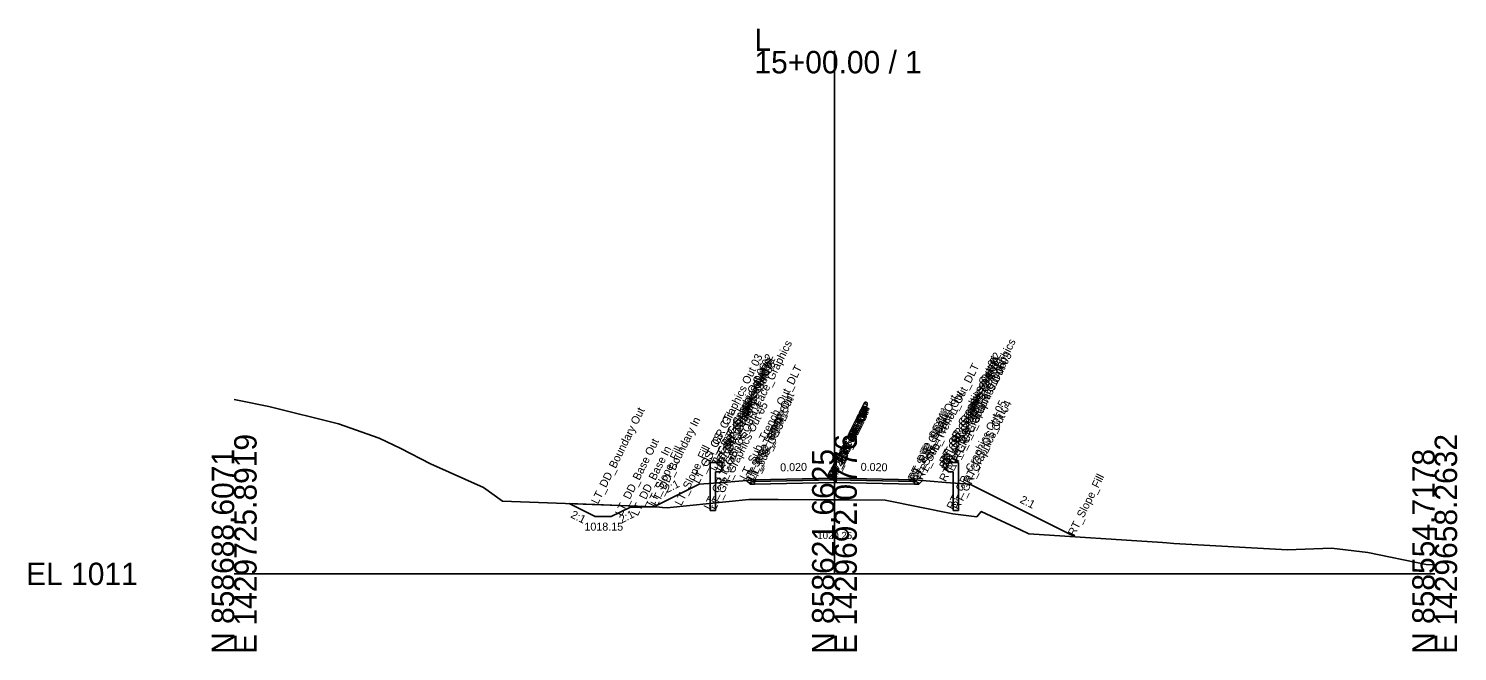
# Model space of a CAD drawing. Extents: x -26 to 153, y -10 to 13058.
# Drawn here: x -25.7 to 152.8, y 6990.3 to 7068.1 of the extents above; entities that cross this region are included whole.
import ezdxf

# ---------------------------------------------------------------- set-up
doc = ezdxf.new("R2010")
doc.units = 0
for name, color, linetype in [('Default', 7, 'Continuous'), ('Exist Cross Section Cell', 7, 'Continuous'), ('Exist XS Ground Line', 7, 'Continuous'), ('Old_Level_50', 7, 'Continuous'), ('Prop CMT Ditch DDE', 7, 'Continuous'), ('Prop CMT Guardrail Graphics', 7, 'Continuous'), ('Prop CMT Pvmt Course 1', 7, 'Continuous'), ('Prop CMT Pvmt Course 2', 7, 'Continuous'), ('Prop CMT Pvmt Surface', 7, 'Continuous'), ('Prop CMT Pvmt Surface Shoulder', 7, 'Continuous'), ('Prop CMT Shld Paved Course 1', 7, 'Continuous'), ('Prop CMT Shld Paved Course 2', 7, 'Continuous'), ('Prop CMT Slope Grass', 7, 'Continuous'), ('Prop CMT Subgrade Daylight Point', 7, 'Continuous'), ('Prop CMT Subgrade Earthwork', 7, 'Continuous'), ('Prop XS Ditch Slope Text', 7, 'Continuous'), ('Prop XS Ditch Standard Text', 7, 'Continuous'), ('Prop XS Dump Level', 7, 'Continuous'), ('Prop XS SE Text', 7, 'Continuous'), ('Prop XS Side Slope Text', 7, 'Continuous')]:
    doc.layers.add(name, color=color, linetype=linetype)

msp = doc.modelspace()

# ---------------------------------------------------------------- linework, layer by layer
at = {"layer": 'Exist Cross Section Cell'}
for p, q in [((75, 7000), (75, 7065.35)), ((0, 7000), (75, 7000)), ((75, 7000), (150, 7000))]:
    msp.add_line(p, q, dxfattribs=at)
at = {"layer": 'Exist XS Ground Line'}
msp.add_lwpolyline([(0, 7021.78), (0.6, 7021.68), (4.31, 7020.91), (13.04, 7018.73), (18.11, 7016.97), (20.83, 7015.68), (24.54, 7013.75), (31.15, 7010.81), (33.52, 7009.1), (51.47, 7008.4), (53.16, 7008.34), (53.53, 7008.29), (54.16, 7008.26), (54.47, 7008.3), (64.29, 7009.29), (67.98, 7009.31), (72.67, 7009.26), (75, 7009.25), (76.9, 7009.24), (81.34, 7009.19), (89.78, 7007.51), (92.77, 7007.11), (93.34, 7007.8), (98.26, 7005.49), (99.29, 7005.02), (115.98, 7003.94), (116.55, 7003.86), (117.4, 7003.81), (131.59, 7002.99), (137.11, 7003.23), (141.63, 7002.65), (148.95, 7001.18), (150, 7001.13)], dxfattribs=at)
at = {"layer": 'Old_Level_50'}
for p, q in [((51.47, 7008.4), (41.87, 7008.78)), ((49.42, 7008.3), (52.42, 7008.36)), ((52.42, 7008.36), (51.47, 7008.4))]:
    msp.add_line(p, q, dxfattribs=at)
msp.add_lwpolyline([(41.87, 7008.78), (45.12, 7007.15), (47.12, 7007.15), (49.42, 7008.3)], dxfattribs=at)
at = {"layer": 'Prop CMT Ditch DDE'}
for points in [[(49.42, 7008.3), (47.12, 7007.15), (45.12, 7007.15), (41.87, 7008.78)], [(49.42, 7008.3), (52.42, 7008.36)]]:
    msp.add_lwpolyline(points, dxfattribs=at)
at = {"layer": 'Prop CMT Guardrail Graphics'}
for points in [[(59.48, 7007.93), (59.48, 7013.93)], [(59.48, 7013.93), (60.81, 7013.93), (61.08, 7013.64)], [(61.08, 7013.06), (60.81, 7012.77), (60.15, 7012.77)], [(60.15, 7012.77), (60.15, 7007.93)], [(61.08, 7013.64), (60.81, 7013.35)], [(60.81, 7013.35), (61.08, 7013.06)], [(90.52, 7013.93), (89.19, 7013.93), (88.92, 7013.64)], [(88.92, 7013.64), (89.19, 7013.35)], [(89.19, 7013.35), (88.92, 7013.06)], [(88.92, 7013.06), (89.19, 7012.77), (89.85, 7012.77)], [(89.85, 7012.77), (89.85, 7007.93)], [(90.52, 7007.93), (90.52, 7013.93)], [(60.15, 7007.93), (59.48, 7007.93)], [(89.85, 7007.93), (90.52, 7007.93)]]:
    msp.add_lwpolyline(points, dxfattribs=at)
at = {"layer": 'Prop CMT Pvmt Course 1'}
for points in [[(75, 7011.95), (65, 7011.75)], [(65, 7011.75), (65, 7011.54)], [(65, 7011.54), (75, 7011.74)], [(75, 7011.74), (75, 7011.95)], [(75, 7011.95), (85, 7011.75)], [(75, 7011.74), (75, 7011.95)], [(85, 7011.54), (75, 7011.74)], [(85, 7011.75), (85, 7011.54)]]:
    msp.add_lwpolyline(points, dxfattribs=at)
msp.add_lwpolyline([(75, 7011.74), (75, 7011.82), (75, 7011.82), (75, 7011.74)], close=True, dxfattribs=at)
msp.add_lwpolyline([(75, 7011.74), (75, 7011.82), (75, 7011.82), (75, 7011.74)], close=True, dxfattribs=at)
at = {"layer": 'Prop CMT Pvmt Course 2'}
for points in [[(75, 7011.74), (65, 7011.54)], [(65, 7011.54), (65, 7011.21)], [(65, 7011.21), (75, 7011.41)], [(75, 7011.41), (75, 7011.74)], [(75, 7011.41), (75, 7011.74)], [(75, 7011.74), (85, 7011.54)], [(85, 7011.21), (75, 7011.41)], [(85, 7011.54), (85, 7011.21)]]:
    msp.add_lwpolyline(points, dxfattribs=at)
at = {"layer": 'Prop CMT Pvmt Surface'}
for points in [[(75, 7011.95), (65, 7011.75)], [(75, 7011.95), (85, 7011.75)]]:
    msp.add_lwpolyline(points, dxfattribs=at)
at = {"layer": 'Prop CMT Pvmt Surface Shoulder'}
for points in [[(65, 7011.75), (65, 7011.75)], [(85, 7011.75), (85, 7011.75)]]:
    msp.add_lwpolyline(points, dxfattribs=at)
at = {"layer": 'Prop CMT Shld Paved Course 1'}
for points in [[(65, 7011.75), (64.79, 7011.53)], [(64.79, 7011.53), (65, 7011.54)], [(65, 7011.75), (65, 7011.75)], [(65, 7011.54), (65, 7011.75)], [(85, 7011.75), (85, 7011.75)], [(85, 7011.75), (85.21, 7011.53)], [(85, 7011.54), (85, 7011.75)], [(85.21, 7011.53), (85, 7011.54)]]:
    msp.add_lwpolyline(points, dxfattribs=at)
at = {"layer": 'Prop CMT Shld Paved Course 2'}
for points in [[(64.79, 7011.53), (64.45, 7011.19)], [(64.45, 7011.19), (65, 7011.21)], [(65, 7011.54), (64.79, 7011.53)], [(64.79, 7011.53), (64.79, 7011.53)], [(65, 7011.21), (65, 7011.54)], [(85, 7011.54), (85.21, 7011.53)], [(85, 7011.21), (85, 7011.54)], [(85.55, 7011.19), (85, 7011.21)], [(85.21, 7011.53), (85.21, 7011.53)], [(85.21, 7011.53), (85.55, 7011.19)]]:
    msp.add_lwpolyline(points, dxfattribs=at)
at = {"layer": 'Prop CMT Slope Grass'}
for points in [[(58.08, 7011.19), (52.42, 7008.36)], [(61.08, 7011.43), (58.08, 7011.19)], [(65, 7011.75), (61.08, 7011.43)], [(85, 7011.75), (88.92, 7011.43)], [(88.92, 7011.43), (91.92, 7011.19)], [(91.92, 7011.19), (105, 7004.65)]]:
    msp.add_lwpolyline(points, dxfattribs=at)
at = {"layer": 'Prop CMT Subgrade Earthwork'}
for points in [[(64.45, 7011.19), (63.98, 7011.67)], [(65, 7011.21), (64.45, 7011.19)], [(75, 7011.41), (65, 7011.21)], [(75, 7011.41), (85, 7011.21)], [(85, 7011.21), (85.55, 7011.19)], [(85.55, 7011.19), (86.02, 7011.67)]]:
    msp.add_lwpolyline(points, dxfattribs=at)

# ---------------------------------------------------------------- texts
at = {"layer": 'Default'}
msp.add_text('-', height=0.0001, dxfattribs=at).set_placement((0, 7000))
at = {"layer": 'Exist Cross Section Cell'}
for s, p in [('L', (65, 7065.35)), ('15+00.00 / 1', (65, 7062.55)), ('EL 1011', (-26, 6998.6))]:
    msp.add_text(s, height=2.8, dxfattribs=at).set_placement(p)
for s, p in [('E 1429725.8919', (2.8, 6990)), ('E 1429692.0776', (77.8, 6990)), ('E 1429658.2632', (152.8, 6990)), ('N 858688.6071', (0, 6990)), ('N 858621.6625', (75, 6990)), ('N 858554.7178', (150, 6990))]:
    msp.add_text(s, height=2.8, rotation=90, dxfattribs=at).set_placement(p)
at = {"layer": 'Prop CMT Subgrade Daylight Point'}
msp.add_text('1020.25', height=0.9, dxfattribs=at).set_placement((72.86, 7004.35))
at = {"layer": 'Prop XS Ditch Slope Text'}
for rotation, p in [(333.4349, (41.96, 7007.09)), (26.5651, (48.42, 7006.3))]:
    msp.add_text('2:1', height=1, rotation=rotation, dxfattribs=at).set_placement(p)
at = {"layer": 'Prop XS Ditch Standard Text'}
msp.add_text('1018.15', height=1, dxfattribs=at).set_placement((43.76, 7005.4))
at = {"layer": 'Prop XS Dump Level'}
for s, p in [('LT_GS_OS_GR_Face_Graphics', (61.08, 7011.43)), ('RT_GS_OS_GR_Face_Graphics', (88.92, 7011.43)), ('LT_GR_Graphics Out 03', (59.48, 7013.93)), ('LT_GR_Graphics Out 02', (60.81, 7013.93)), ('LT_GR_Graphics Out 01', (61.08, 7013.64)), ('RT_GR_Graphics Out 01', (88.92, 7013.64)), ('RT_GR_Graphics Out 02', (89.19, 7013.93)), ('RT_GR_Graphics Out 09', (89.19, 7013.35)), ('RT_GR_Graphics Out 03', (90.52, 7013.93)), ('LT_GR_Graphics Out 06', (60.15, 7012.77)), ('LT_GR_Graphics Out 09', (60.81, 7013.35)), ('LT_GR_Graphics Out 07', (60.81, 7012.77)), ('LT_GR_Graphics Out 08', (61.08, 7013.06)), ('LT_Sub_Trench_Out_DLT', (63.98, 7011.67)), ('RT_Sub_Trench_Out_DLT', (86.02, 7011.67)), ('RT_GR_Graphics Out 08', (88.92, 7013.06)), ('RT_GR_Graphics Out 07', (89.19, 7012.77)), ('RT_GR_Graphics Out 06', (89.85, 7012.77)), ('LT_Sub_Trench_Out', (64.45, 7011.19)), ('LT_PS2_Shelf_Out', (64.79, 7011.53)), ('RT_PS2_Shelf_Out', (85.21, 7011.53)), ('RT_Sub_Trench_Out', (85.55, 7011.19)), ('RT_GR_Graphics Out 05', (89.85, 7007.93)), ('LT_DD_Boundary Out', (45.44, 7008.63)), ('LT_GS_OS_CTL', (58.08, 7011.19)), ('LT_GR_Graphics Out 04', (59.48, 7007.93)), ('LT_GR_Graphics Out 05', (60.15, 7007.93)), ('LT_PS2_OEOP', (64.79, 7011.53)), ('LT_PV1_OEOT', (65, 7011.75)), ('LT_PS1_OEOP', (65, 7011.75)), ('LT_PV2_OEOT', (65, 7011.54)), ('RT_PV1_OEEOP', (75, 7011.82)), ('RT_PV2_OEEOP', (75, 7011.74)), ('LT_PV1_OEEOP', (75, 7011.82)), ('LT_PV2_OEEOP', (75, 7011.74)), ('RT_Sub_OEEOP', (75, 7011.41)), ('RT_PV1_IEEOP', (75, 7011.82)), ('RT_PV2_IEEOP', (75, 7011.74)), ('LT_Sub_OEEOP', (75, 7011.41)), ('LT_PV1_IEEOP', (75, 7011.82)), ('LT_PV2_IEEOP', (75, 7011.74)), ('RT_PV1_OEOT', (85, 7011.75)), ('RT_PS1_OEOP', (85, 7011.75)), ('RT_PV2_OEOT', (85, 7011.54)), ('RT_Sub_OEOT', (85, 7011.21)), ('RT_PS2_OEOP', (85.21, 7011.53)), ('RT_GR_Graphics Out 04', (90.52, 7007.93)), ('RT_GS_OS_CTL', (91.92, 7011.19)), ('LT_DD_Boundary In', (52.86, 7008.38)), ('LT_Sub_OEOT', (65, 7011.21)), ('LT_DD_Base Out', (48.41, 7007.15)), ('PV1_PGL', (75, 7011.95)), ('PV2_PGL', (75, 7011.74)), ('LT_DD_Base In', (50.41, 7007.15)), ('LT_Slope_Fill', (52.4, 7008.35)), ('LT_Slope_Fill', (55.86, 7008.44)), ('RT_Slope_Fill', (105, 7004.65))]:
    msp.add_text(s, height=1, rotation=63.5833, dxfattribs=at).set_placement(p)
at = {"layer": 'Prop XS SE Text'}
for rotation, p in [(1.1458, (68.23, 7012.81)), (358.8542, (78.27, 7012.88))]:
    msp.add_text('0.020', height=1, rotation=rotation, dxfattribs=at).set_placement(p)
at = {"layer": 'Prop XS Side Slope Text'}
for rotation, p in [(26.5651, (54.08, 7010.09)), (333.4349, (98.09, 7008.95))]:
    msp.add_text('2:1', height=1, rotation=rotation, dxfattribs=at).set_placement(p)

doc.saveas('drawing.dxf')
